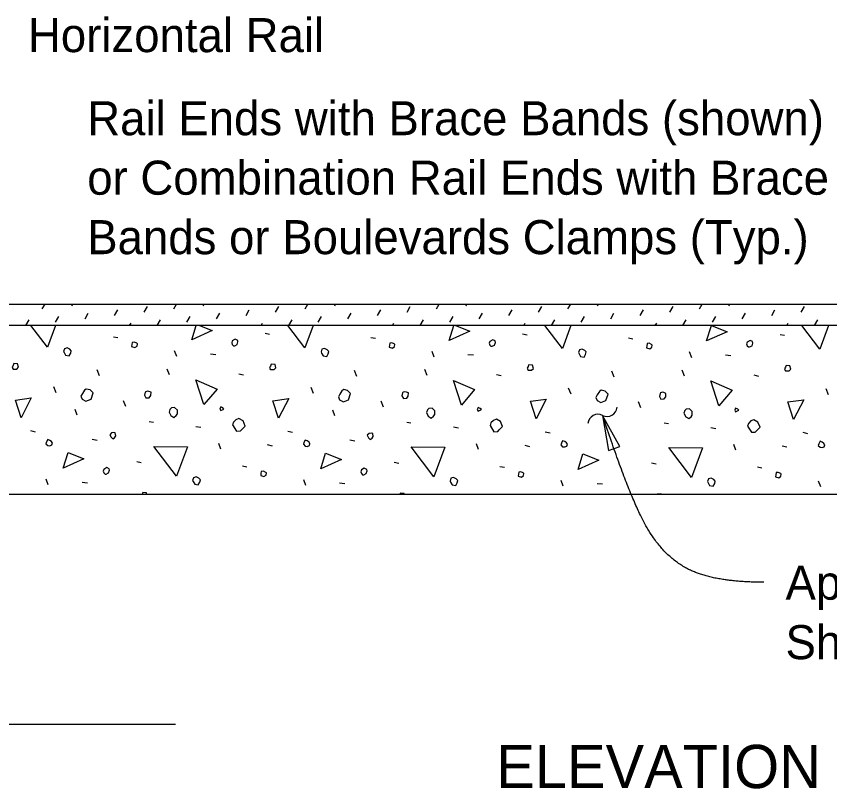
# Model space of a CAD drawing. Extents: x 110341.7 to 110413.5, y 110387.3 to 110417.8.
# Drawn here: x 110348.41 to 110353.225, y 110400.976 to 110405.548 of the extents above; entities that cross this region are included whole.
import ezdxf

# ---------------------------------------------------------------- set-up
doc = ezdxf.new("R2010")
doc.units = 0
for name, color, linetype in [('Border', 7, 'Continuous'), ('Patterning', 7, 'Continuous'), ('PlotBorder_dp', 7, 'Continuous'), ('SheetBorder_dp', 7, 'Continuous')]:
    doc.layers.add(name, color=color, linetype=linetype)

msp = doc.modelspace()

# ---------------------------------------------------------------- linework, layer by layer
at = {"layer": 'Border'}
msp.add_line((110344.5778, 110401.3591), (110349.3523, 110401.3591), dxfattribs=at)
msp.add_lwpolyline([(110351.8806, 110403.1862), (110351.9153, 110402.9778), (110351.982, 110403.0009)], close=True, dxfattribs=at)
for centre, start, end in [((110351.9068, 110403.2392), 243.2317, 354.9589), ((110351.8531, 110403.1327), 63.2317, 174.9589)]:
    msp.add_arc(centre, 0.0596, start, end, dxfattribs=at)
msp.add_open_spline([(110352.8343, 110402.1985), (110352.5689, 110402.1985), (110352.2704, 110402.323), (110352.0548, 110402.655), (110351.8807, 110403.1862)], degree=2, dxfattribs=at)
at = {"layer": 'Patterning'}
for p, q in [((110348.5641, 110403.8158), (110348.5802, 110403.8435)), ((110348.7391, 110403.8352), (110348.744, 110403.8435)), ((110349.1669, 110403.7963), (110349.1864, 110403.8299)), ((110349.342, 110403.8158), (110349.358, 110403.8435)), ((110349.517, 110403.8352), (110349.5218, 110403.8435)), ((110349.9448, 110403.7963), (110349.9642, 110403.8299)), ((110350.1198, 110403.8158), (110350.1358, 110403.8435)), ((110350.2948, 110403.8352), (110350.2996, 110403.8435)), ((110350.7226, 110403.7963), (110350.742, 110403.8299)), ((110350.8976, 110403.8158), (110350.9137, 110403.8435)), ((110351.0726, 110403.8352), (110351.0774, 110403.8435)), ((110351.5004, 110403.7963), (110351.5198, 110403.8299)), ((110351.6754, 110403.8158), (110351.6915, 110403.8435)), ((110351.8504, 110403.8352), (110351.8552, 110403.8435)), ((110352.2782, 110403.7963), (110352.2977, 110403.8299)), ((110352.4532, 110403.8158), (110352.4693, 110403.8435)), ((110352.6282, 110403.8352), (110352.633, 110403.8435)), ((110353.056, 110403.7963), (110353.0755, 110403.8299)), ((110348.8169, 110403.7574), (110348.8364, 110403.791)), ((110348.9919, 110403.7769), (110349.0114, 110403.8105)), ((110349.5947, 110403.7574), (110349.6142, 110403.791)), ((110349.7698, 110403.7769), (110349.7892, 110403.8105)), ((110350.3726, 110403.7574), (110350.392, 110403.791)), ((110350.5476, 110403.7769), (110350.567, 110403.8105)), ((110351.1504, 110403.7574), (110351.1698, 110403.791)), ((110351.3254, 110403.7769), (110351.3448, 110403.8105)), ((110351.9282, 110403.7574), (110351.9476, 110403.791)), ((110352.1032, 110403.7769), (110352.1227, 110403.8105)), ((110352.706, 110403.7574), (110352.7255, 110403.791)), ((110352.881, 110403.7769), (110352.9005, 110403.8105)), ((110348.4669, 110403.7185), (110348.4864, 110403.7521)), ((110348.6419, 110403.738), (110348.6614, 110403.7716)), ((110349.081, 110403.7185), (110349.0892, 110403.7327)), ((110349.2447, 110403.7185), (110349.2642, 110403.7521)), ((110349.4197, 110403.738), (110349.4392, 110403.7716)), ((110349.8588, 110403.7185), (110349.867, 110403.7327)), ((110350.0225, 110403.7185), (110350.042, 110403.7521)), ((110350.1976, 110403.738), (110350.217, 110403.7716)), ((110350.6366, 110403.7185), (110350.6448, 110403.7327)), ((110350.8004, 110403.7185), (110350.8198, 110403.7521)), ((110350.9754, 110403.738), (110350.9948, 110403.7716)), ((110351.4144, 110403.7185), (110351.4226, 110403.7327)), ((110351.5782, 110403.7185), (110351.5976, 110403.7521)), ((110351.7532, 110403.738), (110351.7726, 110403.7716)), ((110352.1922, 110403.7185), (110352.2004, 110403.7327)), ((110352.356, 110403.7185), (110352.3754, 110403.7521)), ((110352.531, 110403.738), (110352.5504, 110403.7716)), ((110352.9701, 110403.7185), (110352.9782, 110403.7327)), ((110353.1338, 110403.7185), (110353.1533, 110403.7521)), ((110348.9851, 110403.6514), (110349.0116, 110403.6461)), ((110349.8831, 110403.6726), (110349.9096, 110403.6673)), ((110350.5089, 110403.6478), (110350.5354, 110403.6425)), ((110351.4069, 110403.6691), (110351.4334, 110403.6637)), ((110352.0327, 110403.6443), (110352.0592, 110403.639)), ((110352.9307, 110403.6655), (110352.9572, 110403.6602)), ((110349.3598, 110403.5347), (110349.3474, 110403.5683)), ((110349.5596, 110403.5506), (110349.5914, 110403.5471)), ((110350.8836, 110403.5312), (110350.8713, 110403.5648)), ((110351.0834, 110403.5471), (110351.1152, 110403.5435)), ((110352.4075, 110403.5276), (110352.3951, 110403.5612)), ((110352.6072, 110403.5435), (110352.639, 110403.54)), ((110348.902, 110403.4198), (110348.8878, 110403.4552)), ((110349.3174, 110403.4251), (110349.3033, 110403.4605)), ((110350.4258, 110403.4163), (110350.4116, 110403.4516)), ((110350.8412, 110403.4216), (110350.8271, 110403.4569)), ((110351.9496, 110403.4127), (110351.9355, 110403.4481)), ((110352.365, 110403.418), (110352.3509, 110403.4534)), ((110349.7275, 110403.4322), (110349.7558, 110403.4251)), ((110351.2513, 110403.4286), (110351.2796, 110403.4216)), ((110352.7751, 110403.4251), (110352.8034, 110403.418)), ((110348.6456, 110403.319), (110348.6315, 110403.3544)), ((110350.1695, 110403.3155), (110350.1553, 110403.3509)), ((110351.6933, 110403.312), (110351.6791, 110403.3473)), ((110353.2171, 110403.3084), (110353.2029, 110403.3438)), ((110349.0593, 110403.2377), (110349.0452, 110403.2731)), ((110350.5831, 110403.2342), (110350.569, 110403.2695)), ((110352.1069, 110403.2306), (110352.0928, 110403.266)), ((110348.7712, 110403.1865), (110348.7588, 110403.22)), ((110350.295, 110403.1829), (110350.2826, 110403.2165)), ((110349.1972, 110403.1493), (110349.2219, 110403.1458)), ((110349.473, 110403.121), (110349.503, 110403.1157)), ((110350.721, 110403.1458), (110350.7458, 110403.1423)), ((110350.9968, 110403.1175), (110351.0268, 110403.1122)), ((110352.2448, 110403.1423), (110352.2696, 110403.1387)), ((110352.5206, 110403.114), (110352.5506, 110403.1087)), ((110348.4936, 110403.0963), (110348.5219, 110403.0892)), ((110350.0174, 110403.0928), (110350.0457, 110403.0857)), ((110351.5412, 110403.0892), (110351.5695, 110403.0822)), ((110353.0651, 110403.0857), (110353.0933, 110403.0786)), ((110348.8595, 110403.045), (110348.8896, 110403.0397)), ((110349.6215, 110402.9867), (110349.6091, 110403.0203)), ((110349.8955, 110403.0132), (110349.9237, 110403.0061)), ((110350.3834, 110403.0415), (110350.4134, 110403.0362)), ((110351.1453, 110402.9832), (110351.1329, 110403.0167)), ((110352.6691, 110402.9796), (110352.6567, 110403.0132)), ((110351.4193, 110403.0097), (110351.4476, 110403.0026)), ((110352.9431, 110403.0061), (110352.9714, 110402.9991)), ((110349.1229, 110402.9124), (110349.1495, 110402.9071)), ((110349.7487, 110402.8877), (110349.7752, 110402.8824)), ((110350.6468, 110402.9089), (110350.6733, 110402.9036)), ((110351.2725, 110402.8842), (110351.2991, 110402.8789)), ((110352.1706, 110402.9054), (110352.1971, 110402.9001)), ((110352.7964, 110402.8806), (110352.8229, 110402.8753)), ((110348.5997, 110402.7746), (110348.5873, 110402.8081)), ((110348.7994, 110402.7905), (110348.8313, 110402.7869)), ((110350.1235, 110402.771), (110350.1111, 110402.8046)), ((110350.3233, 110402.7869), (110350.3551, 110402.7834)), ((110351.6473, 110402.7675), (110351.6349, 110402.8011)), ((110351.8471, 110402.7834), (110351.8789, 110402.7799)), ((110353.1711, 110402.764), (110353.1588, 110402.7975))]:
    msp.add_line(p, q, dxfattribs=at)
for points in [[(110348.5944, 110403.5895), (110348.4963, 110403.7185)], [(110348.6426, 110403.7185), (110348.5944, 110403.5895)], [(110349.4482, 110403.6337), (110349.4743, 110403.7185)], [(110349.4943, 110403.7185), (110349.5702, 110403.6885), (110349.4482, 110403.6337)], [(110350.1182, 110403.586), (110350.0174, 110403.7185)], [(110350.1677, 110403.7185), (110350.1182, 110403.586)], [(110350.972, 110403.6302), (110350.9992, 110403.7185)], [(110351.0092, 110403.7185), (110351.094, 110403.685), (110350.972, 110403.6302)], [(110351.642, 110403.5824), (110351.5386, 110403.7185)], [(110351.6929, 110403.7185), (110351.642, 110403.5824)], [(110352.4958, 110403.6266), (110352.5241, 110403.7185), (110352.6178, 110403.6814), (110352.4958, 110403.6266)], [(110353.1658, 110403.5789), (110353.0597, 110403.7185)], [(110353.218, 110403.7185), (110353.1658, 110403.5789)], [(110349.6957, 110403.5983), (110349.7028, 110403.5983), (110349.7169, 110403.6054), (110349.7222, 110403.6213), (110349.7204, 110403.6302), (110349.7063, 110403.6372), (110349.6886, 110403.6266), (110349.6851, 110403.616), (110349.6886, 110403.6054), (110349.6957, 110403.5983)], [(110349.0929, 110403.593), (110349.1123, 110403.5877), (110349.1247, 110403.5966), (110349.1265, 110403.6089), (110349.1229, 110403.6125), (110349.1088, 110403.6196), (110349.0964, 110403.6178), (110349.0947, 110403.6054), (110349.0929, 110403.593)], [(110350.6167, 110403.5895), (110350.6362, 110403.5842), (110350.6485, 110403.593), (110350.6503, 110403.6054), (110350.6468, 110403.6089), (110350.6326, 110403.616), (110350.6202, 110403.6143), (110350.6185, 110403.6019), (110350.6167, 110403.5895)], [(110351.2195, 110403.5948), (110351.2266, 110403.5948), (110351.2407, 110403.6019), (110351.246, 110403.6178), (110351.2443, 110403.6266), (110351.2301, 110403.6337), (110351.2124, 110403.6231), (110351.2089, 110403.6125), (110351.2124, 110403.6019), (110351.2195, 110403.5948)], [(110352.1405, 110403.586), (110352.16, 110403.5807), (110352.1723, 110403.5895), (110352.1741, 110403.6019), (110352.1706, 110403.6054), (110352.1564, 110403.6125), (110352.1441, 110403.6107), (110352.1423, 110403.5983), (110352.1405, 110403.586)], [(110352.7433, 110403.5913), (110352.7504, 110403.5913), (110352.7645, 110403.5983), (110352.7698, 110403.6143), (110352.7681, 110403.6231), (110352.7539, 110403.6302), (110352.7363, 110403.6196), (110352.7327, 110403.6089), (110352.7363, 110403.5983), (110352.7433, 110403.5913)], [(110348.6934, 110403.5577), (110348.7022, 110403.5418), (110348.7234, 110403.5382), (110348.7323, 110403.5541), (110348.7358, 110403.5683), (110348.727, 110403.5771), (110348.7111, 110403.586), (110348.6951, 110403.5807), (110348.6898, 110403.5648), (110348.6934, 110403.5577)], [(110350.2172, 110403.5541), (110350.226, 110403.5382), (110350.2472, 110403.5347), (110350.2561, 110403.5506), (110350.2596, 110403.5648), (110350.2508, 110403.5736), (110350.2349, 110403.5824), (110350.219, 110403.5771), (110350.2137, 110403.5612), (110350.2172, 110403.5541)], [(110351.741, 110403.5506), (110351.7498, 110403.5347), (110351.7711, 110403.5312), (110351.7799, 110403.5471), (110351.7834, 110403.5612), (110351.7746, 110403.5701), (110351.7587, 110403.5789), (110351.7428, 110403.5736), (110351.7375, 110403.5577), (110351.741, 110403.5506)], [(110348.3911, 110403.4605), (110348.4123, 110403.4605), (110348.4229, 110403.4711), (110348.4176, 110403.4905), (110348.3946, 110403.4923), (110348.3911, 110403.4817), (110348.3858, 110403.4728), (110348.3911, 110403.4605), (110348.3876, 110403.464)], [(110349.9149, 110403.4569), (110349.9361, 110403.4569), (110349.9467, 110403.4675), (110349.9414, 110403.487), (110349.9184, 110403.4887), (110349.9149, 110403.4781), (110349.9096, 110403.4693), (110349.9149, 110403.4569), (110349.9114, 110403.4605)], [(110351.4387, 110403.4534), (110351.4599, 110403.4534), (110351.4705, 110403.464), (110351.4652, 110403.4834), (110351.4423, 110403.4852), (110351.4387, 110403.4746), (110351.4334, 110403.4658), (110351.4387, 110403.4534), (110351.4352, 110403.4569)], [(110352.9625, 110403.4498), (110352.9837, 110403.4498), (110352.9944, 110403.4605), (110352.989, 110403.4799), (110352.9661, 110403.4817), (110352.9625, 110403.4711), (110352.9572, 110403.4622), (110352.9625, 110403.4498), (110352.959, 110403.4534)], [(110349.5207, 110403.2501), (110349.473, 110403.3968), (110349.5985, 110403.342), (110349.5207, 110403.2501)], [(110351.0445, 110403.2466), (110350.9968, 110403.3933), (110351.1223, 110403.3385), (110351.0445, 110403.2466)], [(110352.5683, 110403.243), (110352.5206, 110403.3897), (110352.6461, 110403.3349), (110352.5683, 110403.243)], [(110348.7994, 110403.2819), (110348.8224, 110403.2695), (110348.8525, 110403.2819), (110348.8648, 110403.319), (110348.8472, 110403.3367), (110348.8242, 110403.342), (110348.8136, 110403.3349), (110348.8012, 110403.3155), (110348.7924, 110403.2996), (110348.7994, 110403.2819)], [(110349.1689, 110403.3049), (110349.1777, 110403.289), (110349.1972, 110403.2907), (110349.206, 110403.3031), (110349.2078, 110403.3226), (110349.1954, 110403.3279), (110349.1866, 110403.3296), (110349.176, 110403.3261), (110349.1724, 110403.3226), (110349.1689, 110403.3049)], [(110350.3233, 110403.2784), (110350.3462, 110403.266), (110350.3763, 110403.2784), (110350.3887, 110403.3155), (110350.371, 110403.3332), (110350.348, 110403.3385), (110350.3374, 110403.3314), (110350.325, 110403.312), (110350.3162, 110403.2961), (110350.3233, 110403.2784)], [(110350.6927, 110403.3014), (110350.7016, 110403.2854), (110350.721, 110403.2872), (110350.7298, 110403.2996), (110350.7316, 110403.319), (110350.7192, 110403.3243), (110350.7104, 110403.3261), (110350.6998, 110403.3226), (110350.6963, 110403.319), (110350.6927, 110403.3014)], [(110351.8471, 110403.2748), (110351.8701, 110403.2625), (110351.9001, 110403.2748), (110351.9125, 110403.312), (110351.8948, 110403.3296), (110351.8718, 110403.3349), (110351.8612, 110403.3279), (110351.8488, 110403.3084), (110351.84, 110403.2925), (110351.8471, 110403.2748)], [(110352.2165, 110403.2978), (110352.2254, 110403.2819), (110352.2448, 110403.2837), (110352.2537, 110403.2961), (110352.2554, 110403.3155), (110352.2431, 110403.3208), (110352.2342, 110403.3226), (110352.2236, 110403.319), (110352.2201, 110403.3155), (110352.2165, 110403.2978)], [(110348.4388, 110403.1723), (110348.4052, 110403.2766), (110348.4989, 110403.289), (110348.4388, 110403.1723)], [(110349.9626, 110403.1688), (110349.929, 110403.2731), (110350.0227, 110403.2854), (110349.9626, 110403.1688)], [(110351.4864, 110403.1652), (110351.4529, 110403.2695), (110351.5466, 110403.2819), (110351.4864, 110403.1652)], [(110353.0103, 110403.1617), (110352.9767, 110403.266), (110353.0704, 110403.2784), (110353.0103, 110403.1617)], [(110349.3139, 110403.2059), (110349.3245, 110403.1847), (110349.3421, 110403.1741), (110349.3563, 110403.1847), (110349.3634, 110403.1953), (110349.3634, 110403.2165), (110349.3474, 110403.2324), (110349.328, 110403.2306), (110349.3192, 110403.2218), (110349.3139, 110403.2059)], [(110349.6197, 110403.2147), (110349.6391, 110403.2236), (110349.6321, 110403.2306), (110349.6197, 110403.2359), (110349.6144, 110403.2236), (110349.6197, 110403.2147)], [(110350.8377, 110403.2024), (110350.8483, 110403.1811), (110350.866, 110403.1705), (110350.8801, 110403.1811), (110350.8872, 110403.1918), (110350.8872, 110403.213), (110350.8713, 110403.2289), (110350.8518, 110403.2271), (110350.843, 110403.2183), (110350.8377, 110403.2024)], [(110351.1435, 110403.2112), (110351.1629, 110403.22), (110351.1559, 110403.2271), (110351.1435, 110403.2324), (110351.1382, 110403.22), (110351.1435, 110403.2112)], [(110352.3615, 110403.1988), (110352.3721, 110403.1776), (110352.3898, 110403.167), (110352.4039, 110403.1776), (110352.411, 110403.1882), (110352.411, 110403.2094), (110352.3951, 110403.2253), (110352.3756, 110403.2236), (110352.3668, 110403.2147), (110352.3615, 110403.1988)], [(110352.6673, 110403.2077), (110352.6868, 110403.2165), (110352.6797, 110403.2236), (110352.6673, 110403.2289), (110352.662, 110403.2165), (110352.6673, 110403.2077)], [(110349.6904, 110403.1299), (110349.7134, 110403.0928), (110349.7364, 110403.0945), (110349.7452, 110403.1034), (110349.7646, 110403.1228), (110349.7523, 110403.1529), (110349.7275, 110403.167), (110349.7098, 110403.1599), (110349.6957, 110403.1458), (110349.6904, 110403.1299)], [(110351.2142, 110403.1263), (110351.2372, 110403.0892), (110351.2602, 110403.091), (110351.269, 110403.0998), (110351.2885, 110403.1193), (110351.2761, 110403.1493), (110351.2513, 110403.1635), (110351.2337, 110403.1564), (110351.2195, 110403.1423), (110351.2142, 110403.1263)], [(110352.738, 110403.1228), (110352.761, 110403.0857), (110352.784, 110403.0875), (110352.7928, 110403.0963), (110352.8123, 110403.1157), (110352.7999, 110403.1458), (110352.7751, 110403.1599), (110352.7575, 110403.1529), (110352.7433, 110403.1387), (110352.738, 110403.1228)], [(110348.9709, 110403.0574), (110348.9815, 110403.0468), (110348.9921, 110403.0539), (110348.9992, 110403.0645), (110348.9957, 110403.0822), (110348.9868, 110403.0839), (110348.9744, 110403.0822), (110348.9638, 110403.0715), (110348.9709, 110403.0574)], [(110350.4947, 110403.0539), (110350.5053, 110403.0433), (110350.5159, 110403.0503), (110350.523, 110403.0609), (110350.5195, 110403.0786), (110350.5106, 110403.0804), (110350.4983, 110403.0786), (110350.4877, 110403.068), (110350.4947, 110403.0539)], [(110348.5961, 110403.0079), (110348.6085, 110403.0061), (110348.6209, 110403.0114), (110348.6244, 110403.022), (110348.6191, 110403.0309), (110348.6085, 110403.038), (110348.5961, 110403.0433), (110348.5891, 110403.0291), (110348.5855, 110403.0185), (110348.5961, 110403.0079)], [(110350.12, 110403.0044), (110350.1323, 110403.0026), (110350.1447, 110403.0079), (110350.1482, 110403.0185), (110350.1429, 110403.0274), (110350.1323, 110403.0344), (110350.12, 110403.0397), (110350.1129, 110403.0256), (110350.1094, 110403.015), (110350.12, 110403.0044)], [(110351.6438, 110403.0008), (110351.6562, 110402.9991), (110351.6685, 110403.0044), (110351.6721, 110403.015), (110351.6668, 110403.0238), (110351.6562, 110403.0309), (110351.6438, 110403.0362), (110351.6367, 110403.022), (110351.6332, 110403.0114), (110351.6438, 110403.0008)], [(110353.1676, 110402.9973), (110353.18, 110402.9955), (110353.1923, 110403.0008), (110353.1959, 110403.0114), (110353.1906, 110403.0203), (110353.18, 110403.0274), (110353.1676, 110403.0327), (110353.1605, 110403.0185), (110353.157, 110403.0079), (110353.1676, 110402.9973)], [(110348.6881, 110402.8736), (110348.7164, 110402.9655), (110348.81, 110402.9284), (110348.6881, 110402.8736)], [(110349.3581, 110402.8258), (110349.2237, 110403.0026), (110349.4235, 110403.0008), (110349.3581, 110402.8258)], [(110350.2119, 110402.87), (110350.2402, 110402.9619), (110350.3339, 110402.9248), (110350.2119, 110402.87)], [(110350.8819, 110402.8223), (110350.7475, 110402.9991), (110350.9473, 110402.9973), (110350.8819, 110402.8223)], [(110352.4057, 110402.8188), (110352.2713, 110402.9955), (110352.4711, 110402.9938), (110352.4057, 110402.8188)], [(110351.7357, 110402.8665), (110351.764, 110402.9584), (110351.8577, 110402.9213), (110351.7357, 110402.8665)], [(110348.9356, 110402.8382), (110348.9426, 110402.8382), (110348.9568, 110402.8453), (110348.9621, 110402.8612), (110348.9603, 110402.87), (110348.9462, 110402.8771), (110348.9285, 110402.8665), (110348.925, 110402.8559), (110348.9285, 110402.8453), (110348.9356, 110402.8382)], [(110350.4594, 110402.8347), (110350.4664, 110402.8347), (110350.4806, 110402.8417), (110350.4859, 110402.8576), (110350.4841, 110402.8665), (110350.47, 110402.8736), (110350.4523, 110402.8629), (110350.4488, 110402.8523), (110350.4523, 110402.8417), (110350.4594, 110402.8347)], [(110349.457, 110402.794), (110349.4659, 110402.7781), (110349.4871, 110402.7746), (110349.4959, 110402.7905), (110349.4995, 110402.8046), (110349.4906, 110402.8135), (110349.4747, 110402.8223), (110349.4588, 110402.817), (110349.4535, 110402.8011), (110349.457, 110402.794)], [(110349.8566, 110402.8294), (110349.876, 110402.8241), (110349.8884, 110402.8329), (110349.8902, 110402.8453), (110349.8866, 110402.8488), (110349.8725, 110402.8559), (110349.8601, 110402.8541), (110349.8583, 110402.8417), (110349.8566, 110402.8294)], [(110350.9809, 110402.7905), (110350.9897, 110402.7746), (110351.0109, 110402.771), (110351.0198, 110402.7869), (110351.0233, 110402.8011), (110351.0145, 110402.8099), (110350.9985, 110402.8188), (110350.9826, 110402.8135), (110350.9773, 110402.7975), (110350.9809, 110402.7905)], [(110351.3804, 110402.8258), (110351.3998, 110402.8205), (110351.4122, 110402.8294), (110351.414, 110402.8417), (110351.4104, 110402.8453), (110351.3963, 110402.8523), (110351.3839, 110402.8506), (110351.3821, 110402.8382), (110351.3804, 110402.8258)], [(110352.9042, 110402.8223), (110352.9236, 110402.817), (110352.936, 110402.8258), (110352.9378, 110402.8382), (110352.9342, 110402.8417), (110352.9201, 110402.8488), (110352.9077, 110402.847), (110352.906, 110402.8347), (110352.9042, 110402.8223)], [(110352.5047, 110402.7869), (110352.5135, 110402.771), (110352.5347, 110402.7675), (110352.5436, 110402.7834), (110352.5471, 110402.7975), (110352.5383, 110402.8064), (110352.5224, 110402.8152), (110352.5064, 110402.8099), (110352.5011, 110402.794), (110352.5047, 110402.7869)], [(110349.1835, 110402.7185), (110349.1813, 110402.7268), (110349.1583, 110402.7286), (110349.1549, 110402.7185)], [(110350.7064, 110402.7185), (110350.7051, 110402.7233), (110350.6821, 110402.7251), (110350.6799, 110402.7185)], [(110352.2292, 110402.7185), (110352.2289, 110402.7198), (110352.2059, 110402.7215), (110352.2049, 110402.7185)]]:
    msp.add_lwpolyline(points, dxfattribs=at)
at = {"layer": 'PlotBorder_dp'}
for p, q in [((110344.5778, 110403.8435), (110356.9648, 110403.8435)), ((110356.9648, 110403.7185), (110344.5778, 110403.7185)), ((110356.9648, 110402.7185), (110344.5778, 110402.7185))]:
    msp.add_line(p, q, dxfattribs=at)

# ---------------------------------------------------------------- texts
at = {"layer": 'Border'}
for s, p in [('Rail Ends with Brace Bands (shown) ', (110348.83, 110404.8441)), ('or Combination Rail Ends with Brace ', (110348.83, 110404.4921)), ('Bands or Boulevards Clamps (Typ.)', (110348.83, 110404.1401)), ('Approach Slab (Flexible Pavement Approach Slab ', (110352.9629, 110402.095)), ('Shown, Rigid Pavement Approach Slab Similar)', (110352.9629, 110401.743))]:
    msp.add_text(s, height=0.2016, dxfattribs=at).set_placement(p)
at = {"layer": 'SheetBorder_dp'}
for s, height, p in [('Horizontal Rail', 0.2016, (110348.479, 110405.3359)), ('ELEVATION AT INSIDE FACE OF CONCRETE PARAPET', 0.256001, (110351.2508, 110400.9799))]:
    msp.add_text(s, height=height, dxfattribs=at).set_placement(p)

doc.saveas('drawing.dxf')
